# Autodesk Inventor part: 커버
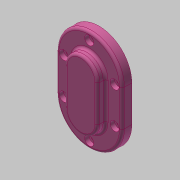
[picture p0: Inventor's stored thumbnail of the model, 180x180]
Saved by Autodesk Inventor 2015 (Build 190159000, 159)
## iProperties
Created: 2019-03
Part Number: 커버
Material: 알루미늄 6061
Document SubType Name: Modeling
Designer: mduedu
Density: 1 g/cm^3
Appearance: 분홍색
Author: mduedu
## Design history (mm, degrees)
sketch "스케치1"
  geometry: L1 (-62, 40)-(62, 40); L2 (62, 40)-(62, -40); L3 (62, -40)-(-62, -40); L4 (-62, -40)-(-62, 40); L5 (-62, 40)-(62, -40); L6 (62, 40)-(-62, -40); 1 further point
  constraints: 12 end point, 2 midpoint, 2 parallel, 1 horizontal, 1 perpendicular
  dimensions: "d59" = 124 distance of L2.end L3.end; "d60" = 80 distance of L1.end L2.end
extrude "돌출1" new body sketch "스케치1" distance "d4" = 12; taper "d5" = 0 deg
fillet "모깎기4"
fillet "모깎기5"
sketch "스케치2"
  geometry: L1 (-20, -22)-(20, -22); L2 (20, -22)-(20, 22); L3 (20, 22)-(-20, 22); L4 (-20, 22)-(-20, -22); L5 (-20, -22)-(20, 22); L6 (20, -22)-(-20, 22); 3 further points
  constraints: 12 end point, 4 midpoint, 2 horizontal alignment, 2 parallel, 1 horizontal, 1 perpendicular, 4 other
  dimensions: "d6" = 40 distance between parallel lines of L2 L4; "d8" = 44 distance between parallel lines of L1 L3
extrude "돌출2" join sketch "스케치2" distance "d9" = 10; taper "d10" = 0 deg
fillet "모깎기2" dims "d12" = 3
sketch "스케치3"
  geometry: L1 (-31, -22)-(31, -22); L2 (31, -22)-(31, 22); L3 (31, 22)-(-31, 22); L4 (-31, 22)-(-31, -22); L5 (-31, -22)-(31, 22); L6 (31, -22)-(-31, 22); A1 r 31 centre (0, 22) between (31, 22) and (0, 53); A2 r 31 centre (0, -22) between (31, -22) and (0, -53); 7 further points
  constraints: 12 end point, 6 midpoint, 4 coincident, 4 point on circle, 2 centre point, 2 parallel, 2 vertical alignment, 1 horizontal, 1 perpendicular
  dimensions: "d76" = 44 distance between parallel lines of L1 L3; "d78" = 62 distance between parallel lines of L2 L4
hole "구멍2" sketch "스케치3" at (0, 53), (31, 22), (31, -22), (-31, -22), (-31, 22), (0, -53) diameter "d28" = 5.5; stored, may be unused: countersink angle "d32" = 90 deg, drill point angle "d34" = 118 deg; dims "d29" = 6, "d30" = 4, "d31" = 2, "d33" = 8
sketch "스케치10"
  geometry: L1 (40, -22)-(40, 22) reference; L2 (-40, 22)-(-40, -22) reference; L3 (23, -22)-(23, 22) reference; L4 (-23, 22)-(-23, -22) reference; C1 r 2.75 at (-31, 22) reference; C2 r 2.75 at (31, -22) reference; C3 r 2.75 at (0, 53) reference; C4 r 2.75 at (31, 22) reference; C5 r 2.75 at (-31, -22) reference; C6 r 2.75 at (0, -53) reference; A1 r 40 centre (0, -22) between (-40, -22) and (40, -22) reference; A2 r 40 centre (0, 22) between (40, 22) and (-40, 22) reference; A3 r 23 centre (0, -22) between (-23, -22) and (23, -22) reference; A4 r 23 centre (0, 22) between (23, 22) and (-23, 22) reference; 7 further points
  constraints: 6 coincident
hole "구멍5" sketch "스케치10" at (0, 53), (31, 22), (31, -22), (0, -53), (-31, -22), (-31, 22) diameter "d79" = 11; stored, may be unused: countersink angle "d83" = 90 deg, drill point angle "d85" = 0 deg; dims "d80" = 6, "d81" = 4, "d82" = 2, "d84" = 5.4
fillet "모깎기3" dims "d68" = 3
sketch "스케치6"
  geometry: C1 r 12.5 at (0, 22); 1 further point
  constraints: 1 centre point, 1 vertical alignment
  dimensions: "d43" = 25 diameter of C1; "d45" = 22 distance of C1.centre point (0, 0)
extrude "돌출5" cut sketch "스케치6" distance "d47" = 15; taper "d48" = 0 deg
node "솔리드1"
mirror "대칭1"
node "투영된 루프5"
